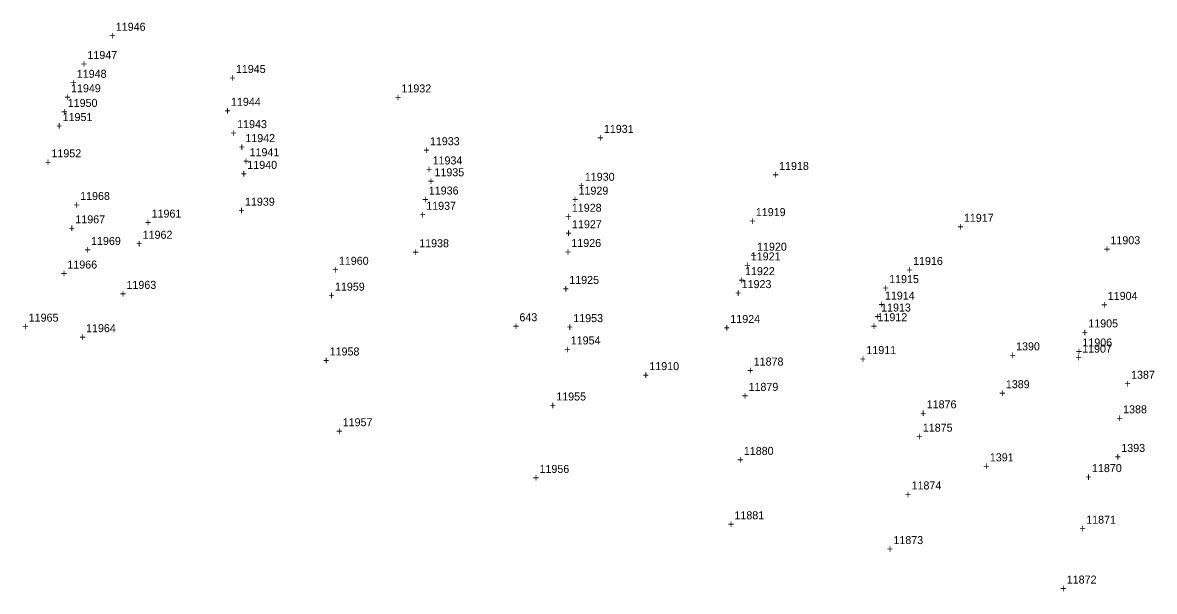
# Model space of a CAD drawing. Extents: x 1160051 to 1162814, y 614604 to 619560.
# Drawn here: x 1160561.4 to 1160915, y 617320.5 to 617498.1 of the extents above; entities that cross this region are included whole.
import ezdxf

# ---------------------------------------------------------------- set-up
doc = ezdxf.new("R2010")
doc.units = 0
for name, color, linetype in [('S_Control_Temp_Traverse', 7, 'Continuous'), ('S_Ground_Elevation', 7, 'Continuous'), ('S_Property_StoneWall', 7, 'Continuous'), ('S_Roadway_Centerline', 7, 'Continuous'), ('S_Roadway_Edge_Pavement', 7, 'Continuous'), ('S_Traffic_Sign_SinglePost', 7, 'Continuous'), ('S_Utilities_Pole_Power', 7, 'Continuous')]:
    doc.layers.add(name, color=color, linetype=linetype)

msp = doc.modelspace()

# ---------------------------------------------------------------- texts
at = {"layer": 'S_Control_Temp_Traverse'}
for s, p in [('643', (1160716.6, 617404.83)), ('+', (1160714.54, 617402.08))]:
    msp.add_text(s, height=2.5, dxfattribs=at).set_placement(p)
at = {"layer": 'S_Ground_Elevation'}
for s, p in [('11946', (1160590.48, 617495.56)), ('+', (1160588.41, 617492.81)), ('11948', (1160578.29, 617480.86)), ('11945', (1160628.01, 617482.37)), ('+', (1160576.23, 617478.11)), ('+', (1160625.95, 617479.62)), ('+', (1160574.43, 617473.6)), ('11949', (1160576.49, 617476.35)), ('+', (1160677.68, 617473.54)), ('11932', (1160679.74, 617476.29)), ('11950', (1160575.46, 617471.76)), ('+', (1160573.4, 617469.01)), ('11943', (1160628.4, 617465.15)), ('11931', (1160742.99, 617463.66)), ('+', (1160626.34, 617462.4)), ('11942', (1160630.96, 617460.77)), ('+', (1160740.93, 617460.91)), ('+', (1160628.9, 617458.02)), ('11941', (1160632.28, 617456.38)), ('+', (1160630.22, 617453.63)), ('11934', (1160689.46, 617453.8)), ('11918', (1160797.74, 617452.08)), ('+', (1160687.4, 617451.05)), ('11935', (1160690.05, 617450.11)), ('+', (1160795.68, 617449.33)), ('+', (1160687.99, 617447.36)), ('+', (1160686.22, 617441.65)), ('11936', (1160688.28, 617444.4)), ('+', (1160733.02, 617441.62)), ('11929', (1160735.08, 617444.37)), ('11928', (1160732.98, 617439.03)), ('11967', (1160577.84, 617435.41)), ('+', (1160730.92, 617436.28)), ('11917', (1160855.48, 617435.88)), ('+', (1160575.78, 617432.66)), ('11962', (1160598.87, 617430.59)), ('+', (1160730.97, 617431.12)), ('11927', (1160733.03, 617433.87)), ('+', (1160853.42, 617433.13)), ('+', (1160596.81, 617427.84)), ('11903', (1160901.27, 617428.87)), ('+', (1160788.8, 617424.11)), ('11921', (1160788.89, 617423.84)), ('11920', (1160790.86, 617426.86)), ('+', (1160899.21, 617426.12)), ('11966', (1160575.35, 617421.28)), ('+', (1160786.83, 617421.09)), ('+', (1160573.29, 617418.53)), ('11922', (1160787.09, 617419.22)), ('11915', (1160832.12, 617416.74)), ('11963', (1160593.82, 617414.94)), ('11959', (1160658.96, 617414.38)), ('+', (1160785.03, 617416.47)), ('+', (1160830.06, 617413.99)), ('+', (1160591.76, 617412.19)), ('+', (1160656.9, 617411.63)), ('11914', (1160830.8, 617411.59)), ('+', (1160828.74, 617408.84)), ('11913', (1160829.61, 617407.86)), ('11965', (1160563.27, 617404.7)), ('+', (1160827.54, 617405.11)), ('11905', (1160894.34, 617402.9)), ('+', (1160561.21, 617401.95)), ('11964', (1160581.19, 617401.41)), ('+', (1160892.28, 617400.15)), ('+', (1160579.13, 617398.66)), ('11954', (1160732.63, 617397.59)), ('11906', (1160892.51, 617396.94)), ('11958', (1160657.3, 617394.13)), ('+', (1160730.57, 617394.84)), ('+', (1160890.37, 617392.26)), ('+', (1160890.45, 617394.19)), ('11907', (1160892.43, 617395.01)), ('+', (1160655.24, 617391.38)), ('11879', (1160788.19, 617383.08)), ('11955', (1160728.11, 617380.08)), ('+', (1160786.12, 617380.33)), ('+', (1160726.05, 617377.33)), ('11957', (1160661.38, 617372.03)), ('+', (1160659.32, 617369.28)), ('+', (1160840.59, 617367.59)), ('11875', (1160842.65, 617370.34)), ('+', (1160784.66, 617360.33)), ('11880', (1160786.72, 617363.08)), ('11956', (1160722.87, 617357.44)), ('11870', (1160895.5, 617357.71)), ('+', (1160720.8, 617354.69)), ('+', (1160893.43, 617354.96)), ('11874', (1160839.12, 617352.29)), ('+', (1160837.06, 617349.54)), ('11881', (1160783.78, 617342.97)), ('+', (1160781.72, 617340.22)), ('11871', (1160893.7, 617341.59)), ('11873', (1160833.46, 617335.23)), ('+', (1160891.64, 617338.84)), ('+', (1160831.4, 617332.48)), ('11872', (1160887.62, 617322.89)), ('+', (1160885.56, 617320.14))]:
    msp.add_text(s, height=2.5, dxfattribs=at).set_placement(p)
at = {"layer": 'S_Property_StoneWall'}
for s, p in [('+', (1160579.56, 617483.98)), ('11947', (1160581.62, 617486.73)), ('11944', (1160626.48, 617472.11)), ('+', (1160624.42, 617469.36)), ('11933', (1160688.63, 617459.81)), ('+', (1160686.57, 617457.06)), ('11930', (1160737.04, 617448.7)), ('+', (1160734.98, 617445.95)), ('11919', (1160790.47, 617437.67)), ('+', (1160788.41, 617434.92)), ('11916', (1160839.6, 617422.4)), ('+', (1160837.54, 617419.65)), ('11904', (1160900.43, 617411.5)), ('+', (1160898.37, 617408.75))]:
    msp.add_text(s, height=2.5, dxfattribs=at).set_placement(p)
at = {"layer": 'S_Roadway_Centerline'}
for s, p in [('11952', (1160570.37, 617456.03)), ('+', (1160568.31, 617453.28)), ('+', (1160628.79, 617438.17)), ('11939', (1160630.85, 617440.92)), ('11938', (1160685.28, 617427.94)), ('+', (1160683.22, 617425.19)), ('11925', (1160732.17, 617416.48)), ('+', (1160730.11, 617413.74)), ('11924', (1160782.5, 617404.29)), ('+', (1160780.43, 617401.54)), ('11911', (1160825.01, 617394.57)), ('+', (1160822.94, 617391.82)), ('1389', (1160868.59, 617383.91)), ('+', (1160866.53, 617381.16)), ('1388', (1160905.23, 617376.07)), ('+', (1160903.17, 617373.32))]:
    msp.add_text(s, height=2.5, dxfattribs=at).set_placement(p)
at = {"layer": 'S_Roadway_Edge_Pavement'}
for s, p in [('11951', (1160573.87, 617467.36)), ('+', (1160571.81, 617464.61)), ('11940', (1160631.58, 617452.42)), ('+', (1160629.52, 617449.67)), ('11968', (1160579.35, 617442.69)), ('+', (1160577.29, 617439.94)), ('11937', (1160687.48, 617439.64)), ('11961', (1160601.66, 617437.19)), ('+', (1160685.42, 617436.89)), ('+', (1160599.6, 617434.44)), ('11926', (1160732.83, 617428.02)), ('+', (1160730.77, 617425.27)), ('11960', (1160660.18, 617422.46)), ('+', (1160658.12, 617419.71)), ('11923', (1160786.04, 617415.18)), ('+', (1160783.98, 617412.43)), ('11953', (1160733.42, 617404.55)), ('11912', (1160828.48, 617404.85)), ('+', (1160731.36, 617401.8)), ('+', (1160826.42, 617402.1)), ('1390', (1160871.79, 617395.74)), ('+', (1160869.73, 617392.99)), ('11878', (1160789.8, 617390.99)), ('+', (1160787.74, 617388.24)), ('1387', (1160907.72, 617386.86)), ('+', (1160905.66, 617384.11)), ('11876', (1160843.86, 617377.63)), ('+', (1160841.79, 617374.88)), ('1393', (1160904.66, 617364.01)), ('+', (1160902.59, 617361.26))]:
    msp.add_text(s, height=2.5, dxfattribs=at).set_placement(p)
at = {"layer": 'S_Traffic_Sign_SinglePost'}
for s, p in [('11910', (1160757.19, 617389.55)), ('+', (1160755.13, 617386.8))]:
    msp.add_text(s, height=2.5, dxfattribs=at).set_placement(p)
at = {"layer": 'S_Utilities_Pole_Power'}
for s, p in [('11969', (1160582.75, 617428.66)), ('+', (1160580.69, 617425.91)), ('1391', (1160863.59, 617361.06)), ('+', (1160861.52, 617358.31))]:
    msp.add_text(s, height=2.5, dxfattribs=at).set_placement(p)

doc.saveas('drawing.dxf')
